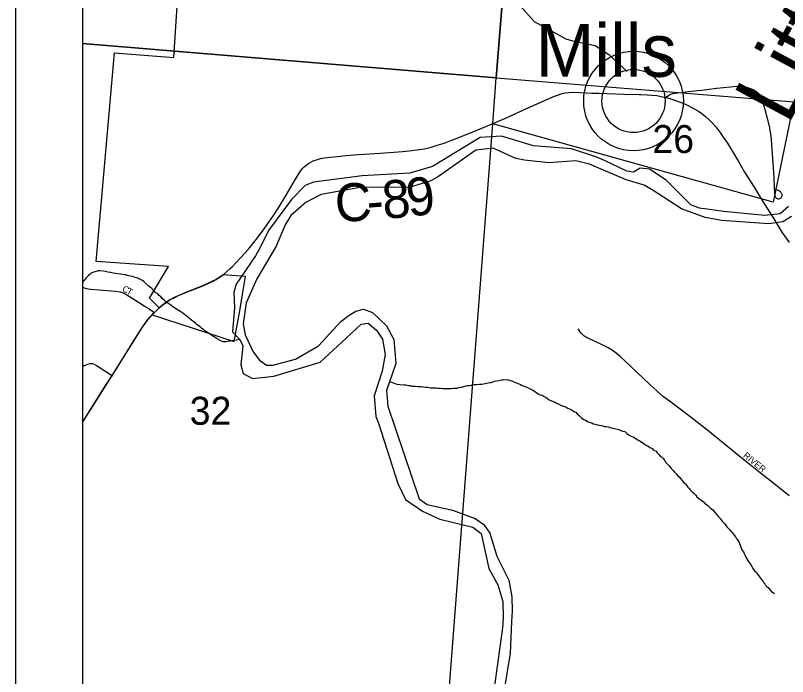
# Model space of a CAD drawing. Extents: x -19.5 to 44.1, y 0 to 22.
# Drawn here: x -19.313 to -18.159, y 18.108 to 19.097 of the extents above; entities that cross this region are included whole.
import ezdxf

# ---------------------------------------------------------------- set-up
doc = ezdxf.new("R2010")
doc.units = 0
for name, color, linetype in [('GM_X_City_Street', 7, 'Continuous'), ('GM_X_City_Street_Text', 7, 'Continuous'), ('GM_X_Corporation', 7, 'Continuous'), ('GM_X_County_Road', 7, 'Continuous'), ('GM_X_County_Road_Text', 7, 'Continuous'), ('GM_X_Major_River', 7, 'Continuous'), ('GM_X_Major_River_Text', 7, 'Continuous'), ('GM_X_Minor_River', 7, 'Continuous'), ('GM_X_Section', 7, 'Continuous'), ('GM_X_Section_Text', 7, 'Continuous'), ('GM_X_Township_Road', 7, 'Continuous'), ('GM_X_Township_Subdivision', 7, 'Continuous'), ('GM_X_Township_Subdivision_Text', 7, 'Continuous'), ('GM_X_Unincorporated', 7, 'Continuous'), ('GM_X_Unincorporated_Location', 7, 'Continuous'), ('GM_X_Unincorporated_Text', 7, 'Continuous'), ('SH_Data', 7, 'Continuous')]:
    doc.layers.add(name, color=color, linetype=linetype)

msp = doc.modelspace()

# ---------------------------------------------------------------- linework, layer by layer
at = {"layer": 'GM_X_City_Street'}
for points in [[(-19.213, 18.6905), (-19.2073, 18.6888), (-19.2042, 18.6881), (-19.2002, 18.6875), (-19.188, 18.6868), (-19.1701, 18.6852), (-19.1631, 18.6847), (-19.1565, 18.6836), (-19.1519, 18.6822), (-19.1482, 18.6804), (-19.1254, 18.6658), (-19.1202, 18.6624), (-19.1135, 18.6581), (-19.1081, 18.6547), (-19.1054, 18.653)], [(-19.1087, 18.6495), (-19.1067, 18.6517), (-19.1054, 18.653)], [(-19.1054, 18.653), (-19.1017, 18.6565), (-19.0993, 18.6586), (-19.0982, 18.6596)], [(-19.213, 18.5722), (-19.2106, 18.5734), (-19.2048, 18.5756), (-19.2012, 18.5764), (-19.1981, 18.5763), (-19.1952, 18.5754), (-19.1919, 18.5736), (-19.1742, 18.5621), (-19.1705, 18.5595), (-19.1687, 18.5582)]]:
    msp.add_lwpolyline(points, dxfattribs=at)
at = {"layer": 'GM_X_Corporation'}
msp.add_line((-19.213, 19.2244), (-19.213, 18.4884), dxfattribs=at)
msp.add_lwpolyline([(-19.213, 18.4884), (-19.1685, 18.5584), (-19.1232, 18.6308), (-19.1154, 18.6417), (-19.1087, 18.6495), (-18.9862, 18.6092), (-18.9777, 18.6554), (-18.9736, 18.6796), (-18.9695, 18.7067), (-19.0028, 18.7092), (-19.0134, 18.7021), (-19.0346, 18.6922), (-19.0577, 18.6832), (-19.0758, 18.675), (-19.0822, 18.6716), (-19.0874, 18.6682), (-19.0902, 18.6661), (-19.0935, 18.6636), (-19.0982, 18.6596), (-19.1127, 18.6742), (-19.0843, 18.7215), (-19.1923, 18.7291), (-19.1648, 19.041), (-19.0765, 19.0339), (-19.0648, 19.2109)], dxfattribs=at)
at = {"layer": 'GM_X_County_Road'}
for points in [[(-18.9923, 18.7185), (-18.9893, 18.7211), (-18.9761, 18.7352), (-18.965, 18.7475), (-18.9568, 18.7574), (-18.9512, 18.7644), (-18.9413, 18.7779), (-18.9273, 18.7977), (-18.9202, 18.8094), (-18.9086, 18.8282), (-18.8982, 18.8461), (-18.8894, 18.8611), (-18.886, 18.8657), (-18.8836, 18.8685), (-18.8815, 18.8707), (-18.8787, 18.8732), (-18.8753, 18.8758), (-18.8719, 18.8778), (-18.868, 18.8798), (-18.862, 18.8816), (-18.8573, 18.8829), (-18.8511, 18.884), (-18.8424, 18.8852), (-18.8326, 18.8862), (-18.8195, 18.8873), (-18.7999, 18.8888), (-18.7681, 18.8912), (-18.7344, 18.8936), (-18.7207, 18.895), (-18.7174, 18.8954), (-18.7126, 18.8961), (-18.7019, 18.8975), (-18.6918, 18.9), (-18.6829, 18.9028), (-18.6723, 18.9058), (-18.6544, 18.913), (-18.6284, 18.9234), (-18.6044, 18.9332), (-18.5785, 18.9442), (-18.5503, 18.9571), (-18.5203, 18.9707), (-18.5102, 18.9752), (-18.5031, 18.9779), (-18.4964, 18.98), (-18.4912, 18.9811), (-18.486, 18.9818), (-18.48, 18.9822), (-18.4604, 18.9814), (-18.4518, 18.9809), (-18.4413, 18.9805), (-18.404, 18.9793), (-18.3812, 18.9786), (-18.3782, 18.9785), (-18.369, 18.9781), (-18.3622, 18.9777), (-18.3547, 18.977), (-18.3485, 18.976), (-18.3417, 18.9745)], [(-18.3417, 18.9745), (-18.3406, 18.9742), (-18.3339, 18.9724), (-18.3269, 18.9699), (-18.317, 18.9663), (-18.3113, 18.9638), (-18.308, 18.9622), (-18.2992, 18.9575), (-18.2927, 18.9538), (-18.2875, 18.9502), (-18.282, 18.946), (-18.2769, 18.9413), (-18.2722, 18.9364), (-18.2669, 18.9302), (-18.2593, 18.9204), (-18.2556, 18.915), (-18.2493, 18.9058), (-18.2371, 18.8858), (-18.2326, 18.8784), (-18.2236, 18.8628), (-18.2093, 18.84), (-18.1972, 18.8204), (-18.1816, 18.7951), (-18.1681, 18.7731), (-18.1618, 18.7639), (-18.157, 18.7575)], [(-19.0028, 18.7092), (-18.9923, 18.7185)], [(-19.0982, 18.6596), (-19.093, 18.664), (-19.0874, 18.6682), (-19.0822, 18.6716), (-19.0761, 18.6749), (-19.0693, 18.6781), (-19.0577, 18.6832), (-19.0367, 18.6913), (-19.0264, 18.6957), (-19.0187, 18.6992), (-19.0134, 18.7021), (-19.0087, 18.705), (-19.0028, 18.7092)], [(-19.1687, 18.5582), (-19.138, 18.6074), (-19.1251, 18.628), (-19.1202, 18.6352), (-19.1146, 18.6427), (-19.1117, 18.6463), (-19.1087, 18.6495)], [(-19.213, 18.4882), (-19.1998, 18.5091), (-19.1774, 18.5449), (-19.1687, 18.5582)]]:
    msp.add_lwpolyline(points, dxfattribs=at)
at = {"layer": 'GM_X_Major_River'}
for points in [[(-18.1581, 18.8111), (-18.1704, 18.8004), (-18.1933, 18.7978), (-18.2546, 18.8037), (-18.2909, 18.8087), (-18.3041, 18.8139), (-18.3409, 18.8508), (-18.3656, 18.8669), (-18.3799, 18.8687), (-18.3895, 18.8628), (-18.3994, 18.8642), (-18.4328, 18.8801), (-18.446, 18.8853), (-18.4821, 18.8975), (-18.5393, 18.9022), (-18.5868, 18.9165), (-18.6187, 18.9145), (-18.6898, 18.8712), (-18.7238, 18.8613), (-18.7952, 18.8572), (-18.8678, 18.8478), (-18.8801, 18.8427), (-18.9006, 18.8219), (-18.935, 18.7752), (-18.9473, 18.75), (-18.9544, 18.7373), (-18.9833, 18.6953), (-18.9866, 18.6829), (-18.9856, 18.6601), (-18.989, 18.6237), (-18.9778, 18.6125), (-18.9735, 18.6029), (-18.9764, 18.5744), (-18.9728, 18.5615), (-18.9589, 18.5543), (-18.927, 18.5578), (-18.8579, 18.5783), (-18.8188, 18.6143), (-18.7964, 18.6351), (-18.7861, 18.6368), (-18.7738, 18.6266), (-18.7646, 18.6131), (-18.7609, 18.5899), (-18.7652, 18.5653), (-18.777, 18.5283)], [(-18.1535, 18.7962), (-18.1665, 18.7885), (-18.1874, 18.7856), (-18.2583, 18.7905), (-18.2828, 18.7948), (-18.3179, 18.8077), (-18.362, 18.8364), (-18.3736, 18.8431), (-18.4004, 18.8509), (-18.4553, 18.8745), (-18.4757, 18.8795), (-18.5163, 18.8766), (-18.5527, 18.8804), (-18.5655, 18.883), (-18.5993, 18.8985), (-18.6252, 18.8957), (-18.681, 18.8559), (-18.6922, 18.8496), (-18.725, 18.8397), (-18.7955, 18.8401), (-18.8561, 18.8293), (-18.8787, 18.818), (-18.9015, 18.798), (-18.9101, 18.7838), (-18.9233, 18.7518), (-18.9524, 18.703), (-18.9683, 18.6673), (-18.9728, 18.6359), (-18.9697, 18.6195), (-18.9577, 18.5938), (-18.9485, 18.5814), (-18.938, 18.574), (-18.9286, 18.5738), (-18.8946, 18.5829), (-18.8601, 18.6027), (-18.8271, 18.6392), (-18.8143, 18.6488), (-18.8047, 18.6546), (-18.7929, 18.6578), (-18.7794, 18.6526), (-18.7585, 18.6327), (-18.7476, 18.6124), (-18.7449, 18.5766)], [(-18.7449, 18.5766), (-18.7586, 18.5359), (-18.7569, 18.5127), (-18.7097, 18.3742), (-18.6977, 18.3656), (-18.6603, 18.3572), (-18.6261, 18.3447), (-18.6134, 18.3357), (-18.6042, 18.3226), (-18.5939, 18.2886), (-18.576, 18.2525), (-18.5712, 18.2277), (-18.5709, 18.2064), (-18.572, 18.1901), (-18.5741, 18.1435), (-18.5838, 18.0825)], [(-18.777, 18.5283), (-18.7746, 18.4975), (-18.7707, 18.4872), (-18.7418, 18.3973), (-18.7302, 18.3732), (-18.7048, 18.3555), (-18.6788, 18.344), (-18.6298, 18.3319), (-18.6174, 18.3225), (-18.606, 18.2698), (-18.5921, 18.2456), (-18.585, 18.2208), (-18.5844, 18.1961), (-18.5855, 18.1813), (-18.5981, 18.0874)]]:
    msp.add_lwpolyline(points, dxfattribs=at)
at = {"layer": 'GM_X_Minor_River'}
for points in [[(-18.8063, 19.4347), (-18.765, 19.4335), (-18.7442, 19.4277), (-18.7229, 19.4116), (-18.7062, 19.3911), (-18.6946, 19.3833), (-18.6599, 19.3726), (-18.649, 19.3686), (-18.628, 19.3533), (-18.6122, 19.3302), (-18.6035, 19.2844), (-18.6076, 19.2511), (-18.6035, 19.2286), (-18.5965, 19.2167), (-18.5857, 19.2039), (-18.5782, 19.16), (-18.5653, 19.1241), (-18.5587, 19.1106), (-18.5379, 19.0881), (-18.491, 19.062), (-18.4808, 19.0588), (-18.4471, 19.052), (-18.4265, 19.0386), (-18.3989, 19.0133)], [(-18.9778, 18.6125), (-18.994, 18.6095), (-18.994, 18.6099), (-18.9986, 18.6088), (-19.0009, 18.6088), (-19.0028, 18.6088), (-19.0054, 18.61), (-19.0073, 18.6108), (-19.0103, 18.6123), (-19.0133, 18.6142), (-19.016, 18.6165), (-19.0179, 18.6173), (-19.0212, 18.62), (-19.0231, 18.6208), (-19.0262, 18.6231), (-19.0284, 18.6243), (-19.0303, 18.6254), (-19.0322, 18.6273), (-19.0348, 18.6289), (-19.0378, 18.632), (-19.0416, 18.6343), (-19.0442, 18.637), (-19.0473, 18.6393), (-19.0503, 18.6416), (-19.0529, 18.6439), (-19.0552, 18.6458), (-19.0578, 18.6477), (-19.0604, 18.6497), (-19.0631, 18.6516), (-19.0661, 18.6539), (-19.0766, 18.6605), (-19.0797, 18.6628), (-19.0827, 18.6651), (-19.0853, 18.6666), (-19.0876, 18.6678), (-19.091, 18.6713), (-19.0936, 18.6739), (-19.0959, 18.6762), (-19.0981, 18.6782), (-19.1004, 18.6805), (-19.1026, 18.6816), (-19.1049, 18.6836), (-19.1071, 18.6866), (-19.1094, 18.6885), (-19.1117, 18.6905), (-19.1143, 18.6924), (-19.1166, 18.6947), (-19.1196, 18.6974), (-19.1211, 18.6993), (-19.1233, 18.7005), (-19.1252, 18.7016), (-19.1279, 18.7028), (-19.1301, 18.704), (-19.1324, 18.7044), (-19.1358, 18.7055), (-19.1384, 18.7067), (-19.1411, 18.7071), (-19.1434, 18.7075), (-19.146, 18.7083), (-19.1479, 18.7091), (-19.1502, 18.7091), (-19.1532, 18.7095), (-19.1562, 18.7099), (-19.1672, 18.7116), (-19.171, 18.7124), (-19.1752, 18.7132), (-19.179, 18.7143), (-19.1816, 18.7147), (-19.1869, 18.7152), (-19.1896, 18.7152), (-19.1957, 18.713), (-19.1995, 18.7123), (-19.2018, 18.7096), (-19.2037, 18.7081), (-19.206, 18.7063), (-19.2079, 18.704), (-19.209, 18.7017), (-19.2113, 18.6999), (-19.213, 18.6975)], [(-18.7544, 18.5495), (-18.7431, 18.5457), (-18.7386, 18.5453), (-18.7325, 18.5448), (-18.7299, 18.5444), (-18.7257, 18.5436), (-18.7234, 18.5436), (-18.7211, 18.5428), (-18.7158, 18.5424), (-18.7117, 18.542), (-18.7094, 18.5419), (-18.7071, 18.5419), (-18.7037, 18.5415), (-18.7003, 18.5411), (-18.6976, 18.5411), (-18.695, 18.5406), (-18.6927, 18.5402), (-18.6901, 18.5402), (-18.6874, 18.5402), (-18.6848, 18.5402), (-18.6821, 18.5398), (-18.6779, 18.5397), (-18.6745, 18.5393), (-18.6715, 18.5393), (-18.6692, 18.5392), (-18.6673, 18.5392), (-18.6639, 18.5392), (-18.6616, 18.5392), (-18.6582, 18.5395), (-18.6555, 18.5395), (-18.6533, 18.5398), (-18.651, 18.5406), (-18.6483, 18.5409), (-18.6464, 18.5413), (-18.6377, 18.5435), (-18.6354, 18.5438), (-18.6324, 18.5442), (-18.6305, 18.5445), (-18.6282, 18.5449), (-18.6244, 18.5452), (-18.6195, 18.5456), (-18.616, 18.5455), (-18.6088, 18.5473), (-18.6043, 18.5481), (-18.6024, 18.548), (-18.5967, 18.5499), (-18.5913, 18.551), (-18.5868, 18.5521), (-18.5845, 18.552), (-18.5788, 18.5524), (-18.5762, 18.5523), (-18.5743, 18.5512), (-18.5716, 18.5508), (-18.5694, 18.5496), (-18.5671, 18.5484), (-18.5648, 18.5476), (-18.5629, 18.5472), (-18.561, 18.5461), (-18.5584, 18.5453), (-18.5558, 18.5438), (-18.552, 18.5422), (-18.549, 18.541), (-18.5403, 18.5364), (-18.5361, 18.5341), (-18.5323, 18.5314), (-18.5289, 18.5298), (-18.5263, 18.529), (-18.5229, 18.5271), (-18.5203, 18.5255), (-18.518, 18.5244), (-18.5157, 18.5224), (-18.512, 18.5209), (-18.5086, 18.5197), (-18.5059, 18.5178), (-18.5021, 18.5162), (-18.498, 18.5143), (-18.4942, 18.5127), (-18.4923, 18.512), (-18.4904, 18.5112), (-18.4878, 18.5096), (-18.4851, 18.5085), (-18.4832, 18.5077), (-18.4814, 18.5065), (-18.478, 18.5042), (-18.4757, 18.5038), (-18.4738, 18.5015), (-18.4704, 18.4981), (-18.4674, 18.4954), (-18.4637, 18.4927), (-18.4614, 18.4919), (-18.4576, 18.4892), (-18.4546, 18.4884), (-18.4519, 18.4876), (-18.4501, 18.4864), (-18.447, 18.4857), (-18.444, 18.4849), (-18.4402, 18.4844), (-18.4383, 18.4837), (-18.4353, 18.4833), (-18.4334, 18.4825), (-18.43, 18.4821)], [(-18.43, 18.4821), (-18.427, 18.4817), (-18.4251, 18.4809), (-18.4179, 18.4793), (-18.4137, 18.4781), (-18.4107, 18.4773), (-18.4084, 18.4765), (-18.4054, 18.4754), (-18.4028, 18.4746), (-18.3997, 18.4719), (-18.396, 18.4692), (-18.3922, 18.4672), (-18.3892, 18.4664), (-18.3858, 18.4641), (-18.3835, 18.4626), (-18.3809, 18.4614), (-18.3779, 18.4587), (-18.376, 18.4583), (-18.3733, 18.456), (-18.3703, 18.4541), (-18.368, 18.4533), (-18.3654, 18.451), (-18.3635, 18.4502), (-18.3616, 18.4495), (-18.3601, 18.4475), (-18.3582, 18.4464), (-18.356, 18.4452), (-18.3545, 18.4429), (-18.3518, 18.4406), (-18.3488, 18.4372), (-18.3462, 18.4364), (-18.3451, 18.4345), (-18.3432, 18.4318), (-18.3413, 18.4287), (-18.3391, 18.4261), (-18.3364, 18.4237), (-18.3346, 18.4211), (-18.3327, 18.4188), (-18.3304, 18.4165), (-18.3282, 18.4138), (-18.3256, 18.4111), (-18.3233, 18.4088), (-18.3214, 18.4073), (-18.3173, 18.4023), (-18.3158, 18.4004), (-18.3139, 18.3977), (-18.312, 18.3965), (-18.3102, 18.3938), (-18.3087, 18.3916), (-18.3064, 18.3896), (-18.3045, 18.3873), (-18.3015, 18.3843), (-18.2989, 18.382), (-18.2966, 18.3797), (-18.2951, 18.377), (-18.2921, 18.3747), (-18.2887, 18.3724), (-18.2853, 18.3697), (-18.2835, 18.3677), (-18.2812, 18.3662), (-18.2786, 18.3643), (-18.2763, 18.3616), (-18.2741, 18.3597), (-18.2714, 18.3581), (-18.2695, 18.3558), (-18.2665, 18.3524), (-18.2643, 18.3493), (-18.2628, 18.347), (-18.2602, 18.3447), (-18.2571, 18.3409), (-18.2553, 18.3386), (-18.2534, 18.3367), (-18.25, 18.3325), (-18.2459, 18.3279), (-18.2444, 18.3259), (-18.2421, 18.3236), (-18.2395, 18.3198), (-18.2373, 18.3171), (-18.2361, 18.3152), (-18.2335, 18.3114), (-18.232, 18.3091), (-18.2276, 18.298), (-18.2253, 18.295), (-18.2242, 18.2923), (-18.2227, 18.2896), (-18.2216, 18.287), (-18.2201, 18.2843), (-18.2186, 18.282), (-18.2171, 18.2789), (-18.2156, 18.277), (-18.213, 18.2728), (-18.2115, 18.2702), (-18.2089, 18.2663), (-18.2066, 18.2644), (-18.2055, 18.2625), (-18.2025, 18.259), (-18.2006, 18.256), (-18.1988, 18.2541), (-18.1957, 18.2506), (-18.195, 18.2487), (-18.1931, 18.2468)], [(-18.1931, 18.2468), (-18.1913, 18.2437), (-18.1886, 18.2418), (-18.1875, 18.2399), (-18.1841, 18.2361), (-18.1807, 18.2334), (-18.1792, 18.2326)]]:
    msp.add_lwpolyline(points, dxfattribs=at)
at = {"layer": 'GM_X_Section'}
for p, q in [((-19.213, 19.8563), (-19.213, 19.055)), ((-19.213, 19.055), (-19.213, 18.0138))]:
    msp.add_line(p, q, dxfattribs=at)
for points in [[(-19.213, 19.055), (-18.595, 19.0037), (-18.5263, 19.8563)], [(-18.5263, 19.8563), (-18.595, 19.0037), (-18.1503, 18.9676), (-17.9131, 19.4312), (-18.0205, 19.8563)], [(-19.213, 18.0138), (-18.6742, 17.9713), (-18.5999, 18.9349), (-18.595, 19.0037), (-19.213, 19.055)]]:
    msp.add_lwpolyline(points, dxfattribs=at)
msp.add_lwpolyline([(-18.595, 19.0037), (-18.1503, 18.9676), (-18.1812, 18.8178), (-18.5999, 18.9349)], close=True, dxfattribs=at)
at = {"layer": 'GM_X_Township_Road'}
msp.add_lwpolyline([(-18.3417, 18.9745), (-18.3371, 18.9777), (-18.3354, 18.9787), (-18.3341, 18.9792), (-18.3326, 18.9797), (-18.3311, 18.98), (-18.3279, 18.9806), (-18.3182, 18.9819), (-18.3081, 18.983), (-18.3026, 18.9836), (-18.2938, 18.9846), (-18.2879, 18.9853), (-18.2803, 18.9862), (-18.2657, 18.9881), (-18.2445, 18.9904), (-18.2358, 18.991), (-18.2302, 18.9909), (-18.2241, 18.9902), (-18.2193, 18.9891), (-18.2147, 18.9876), (-18.2101, 18.9856), (-18.2064, 18.9832), (-18.2039, 18.9811), (-18.2015, 18.9784), (-18.1993, 18.9742), (-18.1978, 18.9704), (-18.1963, 18.9662), (-18.1941, 18.9585), (-18.1914, 18.9487), (-18.1876, 18.9335), (-18.1866, 18.929), (-18.1859, 18.9249), (-18.1847, 18.917), (-18.1835, 18.9046), (-18.1814, 18.8761), (-18.18, 18.8544), (-18.1795, 18.8395), (-18.1792, 18.8314), (-18.1787, 18.8284), (-18.1783, 18.8271), (-18.1779, 18.826), (-18.1774, 18.8252), (-18.1768, 18.8245), (-18.1762, 18.8239), (-18.1754, 18.8234), (-18.1746, 18.8231), (-18.1736, 18.8228), (-18.1727, 18.8228), (-18.1718, 18.8229), (-18.1709, 18.8232), (-18.17, 18.8236), (-18.1692, 18.8242), (-18.1686, 18.8248), (-18.1681, 18.8255), (-18.1678, 18.8264), (-18.1676, 18.8273), (-18.1675, 18.8282), (-18.1677, 18.8292), (-18.1679, 18.83), (-18.1683, 18.8308), (-18.1688, 18.8316), (-18.1693, 18.8322), (-18.1701, 18.833), (-18.1713, 18.834), (-18.1725, 18.8349), (-18.1735, 18.8354), (-18.1746, 18.8358), (-18.1766, 18.8363), (-18.1788, 18.8366)], dxfattribs=at)
at = {"layer": 'GM_X_Township_Subdivision'}
msp.add_lwpolyline([(-18.1569, 18.3788), (-18.1798, 18.3969), (-18.2023, 18.4145), (-18.2323, 18.4386), (-18.2786, 18.4763), (-18.3054, 18.4974), (-18.3158, 18.5053), (-18.3358, 18.52), (-18.3446, 18.5269), (-18.3541, 18.535), (-18.3651, 18.5451), (-18.3939, 18.5725), (-18.4094, 18.5868), (-18.4155, 18.592), (-18.4214, 18.5963), (-18.4273, 18.5997), (-18.4345, 18.6033), (-18.449, 18.6102), (-18.4608, 18.616), (-18.464, 18.6181), (-18.466, 18.6197), (-18.4677, 18.6217), (-18.4701, 18.6252), (-18.4725, 18.6286)], dxfattribs=at)
at = {"layer": 'GM_X_Unincorporated'}
for radius in [0.0744, 0.0472]:
    msp.add_circle((-18.3896, 18.969), radius, dxfattribs=at)
at = {"layer": 'GM_X_Unincorporated_Location'}
msp.add_line((-18.3896, 18.969), (-18.3896, 18.969), dxfattribs=at)
at = {"layer": 'SH_Data'}
for p, q in [((-19.313, 21), (-19.313, 14)), ((-19.213, 19.8563), (-19.213, 14.1))]:
    msp.add_line(p, q, dxfattribs=at)

# ---------------------------------------------------------------- texts
at = {"layer": 'GM_X_City_Street_Text'}
for s, rotation, p in [('C', 332.9733, (-19.1544, 18.6852)), ('T', 331.4615, (-19.1478, 18.6818))]:
    msp.add_text(s, height=0.00947, rotation=rotation, dxfattribs=at).set_placement(p)
at = {"layer": 'GM_X_County_Road_Text'}
for s, rotation, p in [('8', 4.768, (-18.763, 18.7925)), ('9', 7.3649, (-18.7253, 18.7957)), ('C', 3.6752, (-18.834, 18.7876)), ('-', 4.6707, (-18.7863, 18.7906))]:
    msp.add_text(s, height=0.0568, rotation=rotation, dxfattribs=at).set_placement(p)
at = {"layer": 'GM_X_Major_River_Text'}
msp.add_text('Little', height=0.09468, rotation=61.6478, dxfattribs=at).set_placement((-18.1589, 18.9317))
at = {"layer": 'GM_X_Section_Text'}
for s, p in [('26', (-18.3614, 18.8912)), ('32', (-19.0527, 18.4849))]:
    msp.add_text(s, height=0.04186, rotation=0, dxfattribs=at).set_placement(p)
at = {"layer": 'GM_X_Township_Subdivision_Text'}
msp.add_text('RIVER', height=0.00947, rotation=320.711, dxfattribs=at).set_placement((-18.2266, 18.4375))
at = {"layer": 'GM_X_Unincorporated_Text'}
msp.add_text('Mills', height=0.07898, rotation=0, dxfattribs=at).set_placement((-18.536, 19.0052))

doc.saveas('drawing.dxf')
